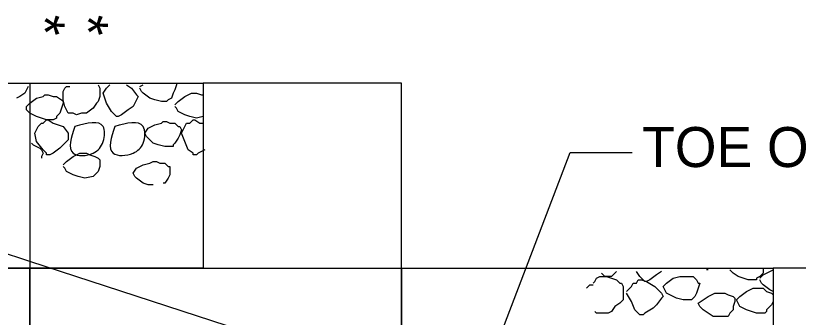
# Model space of a CAD drawing. Extents: x 593 to 1473, y 721 to 1315.
# Drawn here: x 1021.9 to 1080.6, y 1030.5 to 1053.1 of the extents above; entities that cross this region are included whole.
import ezdxf

# ---------------------------------------------------------------- set-up
doc = ezdxf.new("R2010")
doc.units = 0
doc.layers.add('2', color=7, linetype='Continuous')

msp = doc.modelspace()

# ---------------------------------------------------------------- linework, layer by layer
at = {"layer": '2'}
for p, q in [((1022.945, 1048.085), (1022.945, 1006.335)), ((1056.195, 1023.835), (1063.465, 1042.892)), ((1063.465, 1042.892), (1068.138, 1042.892)), ((1022.945, 1034.71), (1010.32, 1038.835)), ((1095.945, 1010.96), (1022.945, 1034.71)), ((994.195, 1034.21), (1022.945, 1034.21))]:
    msp.add_line(p, q, dxfattribs=at)
for points in [[(1022.945, 1034.21), (1008.07, 1034.21), (1008.07, 1048.085), (1022.945, 1048.085)], [(1022.945, 1048.085), (1035.945, 1048.085), (1035.945, 1034.21), (1022.945, 1034.21)], [(1028.07, 1047.96), (1028.195, 1047.71)], [(1028.695, 1047.71), (1028.945, 1047.96)], [(1028.945, 1047.96), (1028.945, 1047.96)], [(1030.195, 1047.96), (1030.57, 1047.71)], [(1031.195, 1047.835), (1031.445, 1047.96)], [(1033.945, 1047.96), (1033.82, 1047.585)], [(1033.945, 1048.085), (1033.945, 1047.96)], [(1022.82, 1047.835), (1022.57, 1047.335)], [(1022.82, 1047.835), (1022.82, 1047.835)], [(1025.445, 1047.46), (1025.57, 1047.71)], [(1025.445, 1047.21), (1025.445, 1047.46)], [(1025.57, 1047.71), (1025.695, 1047.835)], [(1025.695, 1047.835), (1025.945, 1047.835)], [(1028.195, 1047.71), (1028.195, 1047.335)], [(1028.445, 1047.335), (1028.695, 1047.71)], [(1030.57, 1047.71), (1030.945, 1047.21)], [(1031.32, 1047.46), (1031.195, 1047.71)], [(1031.445, 1047.335), (1031.32, 1047.46)], [(1033.82, 1047.585), (1033.695, 1047.335)], [(1022.195, 1047.085), (1021.945, 1046.96)], [(1022.57, 1047.335), (1022.195, 1047.085)], [(1022.945, 1046.585), (1023.445, 1046.96)], [(1023.445, 1046.96), (1023.945, 1047.085)], [(1023.945, 1047.085), (1024.07, 1047.21)], [(1024.07, 1047.21), (1024.32, 1047.21)], [(1024.32, 1047.21), (1024.695, 1047.085)], [(1024.695, 1047.085), (1024.945, 1047.085)], [(1024.945, 1047.085), (1025.32, 1046.835)], [(1025.32, 1046.835), (1025.445, 1046.71)], [(1025.445, 1046.835), (1025.445, 1047.21)], [(1025.57, 1046.335), (1025.445, 1046.835)], [(1028.195, 1047.085), (1028.07, 1046.71)], [(1028.195, 1047.335), (1028.195, 1047.21)], [(1028.195, 1047.21), (1028.195, 1047.085)], [(1028.695, 1046.585), (1028.445, 1047.335)], [(1030.945, 1046.835), (1030.695, 1046.335)], [(1030.945, 1047.21), (1031.07, 1047.085)], [(1031.07, 1047.085), (1030.945, 1046.835)], [(1031.945, 1046.96), (1031.445, 1047.335)], [(1032.32, 1046.835), (1031.945, 1046.96)], [(1032.82, 1046.71), (1032.32, 1046.835)], [(1033.32, 1046.835), (1033.195, 1046.71)], [(1033.57, 1046.96), (1033.32, 1046.835)], [(1033.695, 1047.335), (1033.57, 1046.96)], [(1034.07, 1046.71), (1034.57, 1047.085)], [(1034.57, 1047.085), (1035.07, 1047.335)], [(1035.07, 1047.335), (1035.195, 1047.335)], [(1035.195, 1047.335), (1035.445, 1047.335)], [(1035.445, 1047.335), (1035.82, 1047.21)], [(1035.82, 1047.21), (1035.945, 1047.21)], [(1022.695, 1046.335), (1022.945, 1046.585)], [(1022.695, 1046.085), (1022.695, 1046.335)], [(1022.945, 1046.585), (1022.945, 1046.585)], [(1025.32, 1046.21), (1025.195, 1045.835)], [(1025.445, 1046.585), (1025.32, 1046.21)], [(1025.445, 1046.71), (1025.445, 1046.585)], [(1025.695, 1046.085), (1025.57, 1046.335)], [(1027.695, 1046.21), (1027.195, 1045.835)], [(1027.945, 1046.585), (1027.695, 1046.21)], [(1028.07, 1046.71), (1027.945, 1046.585)], [(1029.07, 1045.96), (1028.695, 1046.585)], [(1030.695, 1046.335), (1030.32, 1046.085)], [(1033.195, 1046.71), (1032.82, 1046.71)], [(1033.82, 1046.46), (1034.07, 1046.71)], [(1033.945, 1046.21), (1033.82, 1046.335)], [(1034.07, 1045.96), (1033.945, 1046.21)], [(1022.945, 1045.835), (1022.695, 1046.085)], [(1022.945, 1045.835), (1022.945, 1045.835)], [(1023.445, 1045.585), (1022.945, 1045.835)], [(1025.195, 1045.835), (1024.945, 1045.585)], [(1025.82, 1045.835), (1025.695, 1046.085)], [(1026.195, 1045.835), (1025.82, 1045.835)], [(1026.445, 1045.71), (1026.195, 1045.835)], [(1026.82, 1045.835), (1026.445, 1045.71)], [(1027.07, 1045.835), (1026.82, 1045.835)], [(1027.195, 1045.835), (1027.07, 1045.835)], [(1029.32, 1045.71), (1029.07, 1045.96)], [(1029.445, 1045.585), (1029.32, 1045.71)], [(1029.82, 1045.71), (1029.57, 1045.585)], [(1030.32, 1046.085), (1029.82, 1045.71)], [(1034.57, 1045.71), (1034.07, 1045.96)], [(1034.945, 1045.585), (1034.57, 1045.71)], [(1023.82, 1045.46), (1023.445, 1045.585)], [(1023.57, 1044.835), (1023.82, 1045.085)], [(1024.195, 1045.335), (1023.82, 1045.46)], [(1023.82, 1045.085), (1023.945, 1045.085)], [(1023.945, 1045.085), (1024.195, 1045.335)], [(1024.195, 1045.335), (1024.195, 1045.335)], [(1024.195, 1045.335), (1024.32, 1045.335)], [(1024.695, 1045.335), (1024.195, 1045.335)], [(1024.32, 1045.335), (1024.695, 1045.085)], [(1024.945, 1045.46), (1024.695, 1045.335)], [(1024.695, 1045.085), (1025.445, 1044.835)], [(1024.945, 1045.585), (1024.945, 1045.46)], [(1029.57, 1045.585), (1029.445, 1045.585)], [(1032.32, 1044.96), (1032.82, 1045.085)], [(1032.82, 1045.085), (1032.945, 1045.21)], [(1032.945, 1045.21), (1033.195, 1045.21)], [(1033.195, 1045.21), (1033.445, 1045.085)], [(1033.445, 1045.085), (1033.82, 1045.085)], [(1033.82, 1045.085), (1034.07, 1044.835)], [(1034.57, 1044.835), (1034.695, 1045.085)], [(1034.695, 1045.085), (1034.945, 1045.085)], [(1035.445, 1045.46), (1034.945, 1045.585)], [(1034.945, 1045.085), (1035.195, 1045.335)], [(1035.195, 1045.335), (1035.195, 1045.335)], [(1035.195, 1045.335), (1035.32, 1045.335)], [(1035.32, 1045.335), (1035.695, 1045.085)], [(1035.945, 1045.585), (1035.445, 1045.46)], [(1035.695, 1045.085), (1035.945, 1045.085)], [(1035.945, 1045.585), (1035.945, 1045.585)], [(1023.32, 1044.335), (1023.57, 1044.835)], [(1025.445, 1044.835), (1025.82, 1044.335)], [(1031.57, 1044.335), (1031.82, 1044.71)], [(1031.82, 1044.71), (1032.32, 1044.96)], [(1034.07, 1044.835), (1034.195, 1044.835)], [(1034.195, 1044.835), (1034.32, 1044.585)], [(1034.32, 1044.585), (1034.195, 1044.21)], [(1034.32, 1044.335), (1034.57, 1044.835)], [(1023.445, 1043.71), (1023.32, 1044.335)], [(1025.82, 1044.335), (1025.82, 1044.085)], [(1025.82, 1044.085), (1025.82, 1043.835)], [(1031.695, 1044.085), (1031.57, 1044.335)], [(1031.82, 1043.96), (1031.695, 1044.085)], [(1032.195, 1043.585), (1031.82, 1043.96)], [(1034.07, 1043.96), (1033.82, 1043.585)], [(1034.195, 1044.21), (1034.07, 1043.96)], [(1034.57, 1043.71), (1034.32, 1044.335)], [(1023.07, 1043.585), (1023.195, 1043.46)], [(1023.195, 1043.46), (1023.445, 1043.335)], [(1023.945, 1043.085), (1023.445, 1043.71)], [(1023.445, 1043.335), (1023.695, 1043.21)], [(1025.445, 1043.46), (1025.195, 1043.21)], [(1025.82, 1043.835), (1025.445, 1043.46)], [(1032.57, 1043.46), (1032.195, 1043.585)], [(1033.07, 1043.335), (1032.57, 1043.46)], [(1033.695, 1043.335), (1033.07, 1043.335)], [(1033.82, 1043.585), (1033.695, 1043.46)], [(1033.695, 1043.46), (1033.695, 1043.335)], [(1034.82, 1043.085), (1034.57, 1043.71)], [(1023.695, 1043.21), (1023.82, 1043.085)], [(1023.82, 1043.085), (1023.945, 1042.835)], [(1023.945, 1042.835), (1023.82, 1042.585)], [(1024.195, 1042.835), (1023.945, 1043.085)], [(1024.195, 1042.71), (1024.195, 1042.835)], [(1024.445, 1042.71), (1024.195, 1042.71)], [(1024.695, 1042.835), (1024.445, 1042.71)], [(1025.195, 1043.21), (1024.695, 1042.835)], [(1026.195, 1042.585), (1026.695, 1042.835)], [(1026.695, 1042.835), (1026.945, 1042.835)], [(1026.945, 1042.835), (1027.195, 1042.835)], [(1027.195, 1042.835), (1027.445, 1042.71)], [(1027.445, 1042.71), (1027.82, 1042.585)], [(1035.195, 1042.835), (1034.82, 1043.085)], [(1035.195, 1042.71), (1035.195, 1042.835)], [(1035.445, 1042.71), (1035.195, 1042.71)], [(1035.57, 1042.835), (1035.445, 1042.71)], [(1036.07, 1043.085), (1035.57, 1042.835)], [(1023.82, 1042.585), (1023.82, 1042.46)], [(1025.445, 1041.96), (1025.695, 1042.21)], [(1025.695, 1042.21), (1026.195, 1042.585)], [(1027.82, 1042.585), (1028.07, 1042.46)], [(1028.07, 1042.46), (1028.195, 1042.335)], [(1028.195, 1042.335), (1028.195, 1042.085)], [(1028.195, 1042.085), (1028.195, 1041.835)], [(1031.445, 1041.96), (1031.945, 1042.085)], [(1031.945, 1042.085), (1032.195, 1042.21)], [(1032.195, 1042.21), (1032.445, 1042.21)], [(1032.445, 1042.21), (1032.695, 1042.085)], [(1032.695, 1042.085), (1033.07, 1042.085)], [(1033.07, 1042.085), (1033.32, 1041.835)], [(1025.57, 1041.71), (1025.445, 1041.835)], [(1025.695, 1041.46), (1025.57, 1041.71)], [(1028.195, 1041.835), (1028.07, 1041.46)], [(1030.695, 1041.335), (1030.945, 1041.71)], [(1030.945, 1041.71), (1031.445, 1041.96)], [(1033.32, 1041.835), (1033.445, 1041.835)], [(1033.445, 1041.835), (1033.445, 1041.585)], [(1033.445, 1041.585), (1033.445, 1041.21)], [(1026.195, 1041.21), (1025.695, 1041.46)], [(1026.57, 1041.085), (1026.195, 1041.21)], [(1027.07, 1040.96), (1026.57, 1041.085)], [(1027.695, 1041.085), (1027.07, 1040.96)], [(1027.82, 1041.21), (1027.695, 1041.085)], [(1027.695, 1041.085), (1027.695, 1041.085)], [(1028.07, 1041.46), (1027.82, 1041.21)], [(1030.82, 1041.085), (1030.695, 1041.335)], [(1030.945, 1040.96), (1030.82, 1041.085)], [(1031.445, 1040.585), (1030.945, 1040.96)], [(1033.32, 1040.96), (1033.07, 1040.585)], [(1033.445, 1041.21), (1033.32, 1040.96)], [(1031.82, 1040.46), (1031.445, 1040.585)], [(1032.195, 1040.46), (1031.82, 1040.46)], [(1033.07, 1040.585), (1032.945, 1040.585)], [(1022.945, 1020.21), (1022.945, 1020.21), (1022.945, 1034.21), (1022.945, 1034.21)], [(1022.945, 1034.21), (1050.82, 1034.21), (1050.82, 1020.21), (1022.945, 1020.21)], [(1066.945, 1033.96), (1066.57, 1033.585)], [(1068.695, 1033.585), (1068.445, 1033.96)], [(1070.32, 1033.96), (1069.945, 1033.71)], [(1070.32, 1033.96), (1070.32, 1033.96)], [(1073.82, 1034.085), (1073.695, 1034.085)], [(1073.695, 1034.085), (1073.695, 1034.085)], [(1073.82, 1034.085), (1073.82, 1034.085)], [(1075.695, 1033.835), (1075.445, 1034.085)], [(1075.445, 1034.085), (1075.445, 1034.085)], [(1077.945, 1034.21), (1077.945, 1033.835)], [(1077.945, 1033.71), (1078.445, 1033.96)], [(1078.445, 1033.96), (1078.695, 1034.085)], [(1065.32, 1033.21), (1065.445, 1033.46)], [(1065.445, 1033.46), (1065.695, 1033.585)], [(1065.695, 1033.585), (1066.195, 1033.585)], [(1066.07, 1033.585), (1065.82, 1033.835)], [(1065.82, 1033.835), (1065.82, 1033.835)], [(1066.195, 1033.585), (1066.07, 1033.585)], [(1066.195, 1033.585), (1066.57, 1033.46)], [(1066.32, 1033.585), (1066.195, 1033.585)], [(1066.57, 1033.585), (1066.32, 1033.585)], [(1066.57, 1033.46), (1066.945, 1033.335)], [(1066.945, 1033.335), (1067.195, 1033.085)], [(1068.445, 1033.085), (1068.57, 1033.335)], [(1068.57, 1033.335), (1068.695, 1033.335)], [(1068.945, 1033.335), (1068.695, 1033.585)], [(1068.695, 1033.335), (1068.82, 1033.335)], [(1068.82, 1033.335), (1069.195, 1033.21)], [(1069.07, 1033.21), (1068.945, 1033.335)], [(1069.445, 1033.335), (1069.195, 1033.21)], [(1069.945, 1033.71), (1069.445, 1033.335)], [(1070.695, 1033.085), (1071.195, 1033.46)], [(1071.195, 1033.46), (1071.695, 1033.585)], [(1071.695, 1033.585), (1071.82, 1033.585)], [(1071.82, 1033.585), (1072.195, 1033.585)], [(1072.195, 1033.585), (1072.32, 1033.585)], [(1072.32, 1033.585), (1072.695, 1033.585)], [(1072.695, 1033.585), (1072.945, 1033.335)], [(1072.945, 1033.335), (1073.07, 1033.085)], [(1076.07, 1033.585), (1075.695, 1033.835)], [(1076.445, 1033.46), (1076.07, 1033.585)], [(1076.82, 1033.335), (1076.445, 1033.46)], [(1077.445, 1033.335), (1076.82, 1033.335)], [(1077.695, 1033.585), (1077.445, 1033.46)], [(1077.445, 1033.46), (1077.445, 1033.335)], [(1077.945, 1033.835), (1077.695, 1033.585)], [(1077.695, 1033.46), (1077.945, 1033.71)], [(1077.82, 1033.085), (1077.695, 1033.335)], [(1064.695, 1032.71), (1064.82, 1032.835)], [(1064.82, 1032.835), (1064.945, 1032.96)], [(1064.945, 1032.96), (1065.195, 1032.96)], [(1065.195, 1033.085), (1065.32, 1033.21)], [(1067.195, 1033.085), (1067.32, 1033.085)], [(1067.32, 1033.085), (1067.445, 1032.835)], [(1067.445, 1032.835), (1067.445, 1032.46)], [(1067.695, 1032.46), (1068.07, 1032.835)], [(1068.07, 1032.835), (1068.195, 1033.085)], [(1068.195, 1033.085), (1068.445, 1033.085)], [(1069.195, 1033.21), (1069.07, 1033.21)], [(1069.195, 1033.21), (1069.82, 1032.835)], [(1069.82, 1032.835), (1070.32, 1032.335)], [(1070.445, 1032.835), (1070.695, 1033.085)], [(1070.57, 1032.585), (1070.445, 1032.835)], [(1073.07, 1032.71), (1072.945, 1032.335)], [(1073.07, 1033.085), (1073.195, 1033.085)], [(1073.195, 1033.085), (1073.07, 1032.71)], [(1076.695, 1032.46), (1077.195, 1032.71)], [(1077.195, 1032.71), (1077.32, 1032.71)], [(1077.32, 1032.71), (1077.57, 1032.71)], [(1077.57, 1032.71), (1077.945, 1032.71)], [(1077.945, 1032.96), (1077.82, 1033.085)], [(1078.445, 1032.585), (1077.945, 1032.96)], [(1077.945, 1032.71), (1078.195, 1032.46)], [(1067.445, 1032.46), (1067.445, 1032.335)], [(1067.445, 1032.335), (1067.445, 1032.085)], [(1068.07, 1031.71), (1067.695, 1032.335)], [(1070.32, 1032.335), (1070.445, 1032.085)], [(1070.695, 1032.335), (1070.57, 1032.585)], [(1071.195, 1032.085), (1070.695, 1032.335)], [(1072.945, 1032.335), (1072.82, 1032.085)], [(1073.82, 1032.085), (1074.32, 1032.335)], [(1074.32, 1032.335), (1074.445, 1032.335)], [(1074.445, 1032.335), (1074.82, 1032.335)], [(1074.82, 1032.335), (1075.07, 1032.335)], [(1075.07, 1032.335), (1075.32, 1032.21)], [(1075.32, 1032.21), (1075.695, 1032.085)], [(1076.195, 1032.085), (1076.695, 1032.46)], [(1078.195, 1032.46), (1078.57, 1032.335)], [(1078.695, 1032.46), (1078.445, 1032.585)], [(1078.57, 1032.335), (1078.695, 1032.21)], [(1078.695, 1032.21), (1078.695, 1032.085)], [(1067.195, 1031.585), (1066.82, 1031.335)], [(1067.445, 1031.835), (1067.195, 1031.585)], [(1067.445, 1032.085), (1067.445, 1031.835)], [(1068.32, 1031.085), (1068.07, 1031.71)], [(1070.32, 1031.96), (1069.945, 1031.46)], [(1070.445, 1032.085), (1070.32, 1031.96)], [(1071.445, 1031.96), (1071.195, 1032.085)], [(1071.945, 1031.835), (1071.445, 1031.96)], [(1072.57, 1031.835), (1071.945, 1031.835)], [(1072.695, 1031.96), (1072.57, 1031.835)], [(1072.82, 1032.085), (1072.695, 1031.96)], [(1073.07, 1031.585), (1073.445, 1031.835)], [(1073.195, 1031.335), (1073.07, 1031.585)], [(1073.445, 1031.835), (1073.82, 1032.085)], [(1075.695, 1032.085), (1075.82, 1031.96)], [(1075.82, 1031.71), (1075.695, 1031.335)], [(1075.82, 1031.96), (1075.82, 1031.71)], [(1075.945, 1031.835), (1076.195, 1032.085)], [(1076.07, 1031.585), (1075.945, 1031.835)], [(1076.195, 1031.335), (1076.07, 1031.585)], [(1078.695, 1031.71), (1078.57, 1031.46)], [(1078.695, 1032.085), (1078.695, 1031.71)], [(1065.445, 1030.835), (1065.32, 1030.96)], [(1066.57, 1030.96), (1066.32, 1030.835)], [(1066.82, 1031.335), (1066.57, 1030.96)], [(1068.57, 1030.835), (1068.32, 1031.085)], [(1069.695, 1031.21), (1069.07, 1030.835)], [(1069.945, 1031.46), (1069.695, 1031.21)], [(1073.445, 1031.085), (1073.195, 1031.335)], [(1073.82, 1030.835), (1073.445, 1031.085)], [(1075.695, 1031.085), (1075.445, 1030.835)], [(1075.695, 1031.335), (1075.695, 1031.085)], [(1076.695, 1031.085), (1076.195, 1031.335)], [(1077.07, 1030.96), (1076.695, 1031.085)], [(1077.445, 1030.835), (1077.07, 1030.96)], [(1078.195, 1030.96), (1078.07, 1030.835)], [(1078.57, 1031.46), (1078.195, 1031.085)], [(1078.195, 1031.085), (1078.195, 1030.96)], [(1065.82, 1030.835), (1065.445, 1030.835)], [(1066.07, 1030.835), (1065.82, 1030.835)], [(1066.32, 1030.835), (1066.07, 1030.835)], [(1068.695, 1030.71), (1068.57, 1030.835)], [(1068.945, 1030.71), (1068.695, 1030.71)], [(1069.07, 1030.835), (1068.945, 1030.71)], [(1074.195, 1030.585), (1073.82, 1030.835)], [(1074.695, 1030.585), (1074.195, 1030.585)], [(1075.195, 1030.585), (1074.695, 1030.585)], [(1075.32, 1030.585), (1075.195, 1030.585)], [(1075.445, 1030.835), (1075.32, 1030.585)], [(1078.07, 1030.835), (1077.445, 1030.835)]]:
    msp.add_lwpolyline(points, dxfattribs=at)
for points in [[(1035.945, 1048.085), (1035.945, 1034.21), (1050.82, 1034.21), (1050.82, 1048.085)], [(1078.695, 1034.21), (1078.695, 1020.21), (1050.82, 1020.21), (1050.82, 1034.21)], [(1078.695, 1034.21), (1078.695, 1020.21), (1085.32, 1020.21), (1085.32, 1034.21)]]:
    msp.add_lwpolyline(points, close=True, dxfattribs=at)
for points in [[(1026.32, 1044.835), (1028.445, 1044.835), (1028.445, 1043.71), (1027.695, 1042.835), (1026.195, 1042.835), (1026.32, 1044.835)], [(1029.32, 1044.835), (1031.445, 1044.835), (1031.445, 1043.585), (1030.695, 1042.835), (1029.195, 1042.835), (1029.32, 1044.835)]]:
    msp.add_spline(points, degree=3, dxfattribs=at)

# ---------------------------------------------------------------- texts
for p in [(1022.57, 1053.21), (1025.82, 1053.21)]:
    msp.add_text('*', height=3, rotation=270, dxfattribs=at).set_placement(p)
msp.add_text('TOE OF EMBANKMENT SLOPE', height=3, dxfattribs=at).set_placement((1068.879, 1041.793))

doc.saveas('drawing.dxf')
